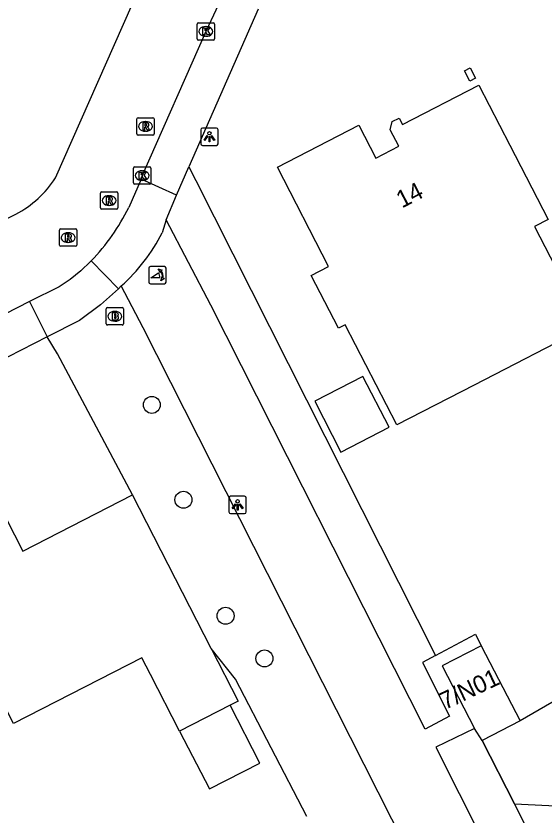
# Model space of a CAD drawing. Extents: x 162722 to 165099, y 384721 to 386283.
# Drawn here: x 163760.74 to 163791.13, y 384830.39 to 384876.43 of the extents above; entities that cross this region are included whole.
import ezdxf

# ---------------------------------------------------------------- set-up
doc = ezdxf.new("R2010")
doc.units = 0
for name, color, linetype in [('IMGEO_Berm_groen', 7, 'Continuous'), ('IMGEO_Boom', 7, 'Continuous'), ('IMGEO_Brandkraan', 7, 'Continuous'), ('IMGEO_Erf', 7, 'Continuous'), ('IMGEO_Fietspad_open', 7, 'Continuous'), ('IMGEO_Groenvoorziening', 7, 'Continuous'), ('IMGEO_Hek', 7, 'Continuous'), ('IMGEO_Kolk', 7, 'Continuous'), ('IMGEO_Lichtpunt', 7, 'Continuous'), ('IMGEO_Pand', 7, 'Continuous'), ('IMGEO_Pand_nummerreeks', 7, 'Continuous'), ('IMGEO_Poller', 7, 'Continuous'), ('IMGEO_Rijbaan_lokaal_open', 7, 'Continuous'), ('IMGEO_Rioolput', 7, 'Continuous'), ('IMGEO_Voetpad_open', 7, 'Continuous')]:
    doc.layers.add(name, color=color, linetype=linetype)

msp = doc.modelspace()

# ---------------------------------------------------------------- linework, layer by layer
at = {"layer": 'IMGEO_Berm_groen'}
for points in [[(164182.287, 385003.976), (164161.635, 384993.222), (164156.397, 384989.2), (164154.232, 384980.18), (163995.614, 384900.161), (163985.449, 384906.254), (163959.707, 384893.04), (163931.557, 384878.59), (163923.156, 384882.979), (163812.864, 384826.88), (163815.437, 384820.076), (163815.184, 384817.086), (163814.501, 384814.338), (163812.895, 384811.778), (163810.688, 384809.881), (163807.775, 384808.947), (163804.957, 384808.683), (163802.157, 384809.847), (163799.68, 384811.721), (163798.176, 384813.594), (163789.435, 384831.038)], [(163767.436, 384848.831), (163763.137, 384856.958), (163762.529, 384857.949)], [(163777.48, 384830.304), (163773.366, 384838.207), (163771.972, 384839.979)], [(163787.572, 384834.681), (163789.435, 384831.038)]]:
    msp.add_lwpolyline(points, dxfattribs=at)
at = {"layer": 'IMGEO_Boom'}
for centre in [(163768.558, 384854.02), (163770.378, 384848.557), (163772.804, 384841.869), (163775.04, 384839.409)]:
    msp.add_circle(centre, 0.489, dxfattribs=at)
at = {"layer": 'IMGEO_Brandkraan'}
for p, q in [((163765.932, 384858.699), (163765.932, 384859.551)), ((163766.007, 384859.625), (163766.859, 384859.625)), ((163766.933, 384859.551), (163766.933, 384858.699)), ((163766.42, 384859.405), (163766.445, 384859.405)), ((163766.859, 384858.625), (163766.007, 384858.625)), ((163766.443, 384858.845), (163766.418, 384858.845))]:
    msp.add_line(p, q, dxfattribs=at)
for points in [[(163765.932, 384858.699), (163765.932, 384859.551)], [(163766.007, 384859.625), (163766.859, 384859.625)], [(163766.933, 384859.551), (163766.933, 384858.699)], [(163766.28, 384859.325), (163766.28, 384858.925), (163766.493, 384858.925)], [(163766.511, 384859.325), (163766.28, 384859.325)], [(163766.459, 384859.244), (163766.405, 384859.244), (163766.405, 384859.168)], [(163766.405, 384859.168), (163766.458, 384859.168)], [(163766.467, 384859.092), (163766.405, 384859.092), (163766.405, 384859.011)], [(163766.859, 384858.625), (163766.007, 384858.625)], [(163766.405, 384859.011), (163766.467, 384859.011)]]:
    msp.add_lwpolyline(points, dxfattribs=at)
for centre, radius, start, end in [((163766.009, 384859.549), 0.0765, 91.552, 178.448), ((163766.009, 384859.549), 0.0765, 91.552, 178.448), ((163766.857, 384859.549), 0.0765, 1.552, 88.448), ((163766.857, 384859.549), 0.0765, 1.552, 88.448), ((163766.46, 384859.206), 0.0379, 267.8285, 90.9355), ((163766.468, 384859.051), 0.0404, 269.8759, 90.5077), ((163766.515, 384859.18), 0.145, 59.4692, 91.5367), ((163766.54, 384859.227), 0.0922, 285.5137, 58.1501), ((163766.545, 384859.035), 0.105, 301.3115, 78.989), ((163766.009, 384858.701), 0.0765, 181.552, 268.448), ((163766.009, 384858.701), 0.0765, 181.552, 268.448), ((163766.499, 384859.176), 0.251, 268.6676, 293.5347), ((163766.857, 384858.701), 0.0765, 271.552, 358.448), ((163766.857, 384858.701), 0.0765, 271.552, 358.448)]:
    msp.add_arc(centre, radius, start, end, dxfattribs=at)
for centre, major_axis, ratio, start_param, end_param in [((163766.419, 384859.125), (-0.387, 0.002), 0.722429, 4.712389, 7.853982), ((163766.444, 384859.125), (-0.39, 0.002), 0.717154, 1.570796, 4.712389)]:
    msp.add_ellipse(centre, major_axis=major_axis, ratio=ratio, start_param=start_param, end_param=end_param, dxfattribs=at)
at = {"layer": 'IMGEO_Erf'}
msp.add_lwpolyline([(163876.056, 384880.802), (163840.837, 384862.308), (163841.154, 384861.667), (163822.396, 384853.228), (163804.848, 384844.548), (163789.755, 384835.805)], dxfattribs=at)
at = {"layer": 'IMGEO_Fietspad_open'}
for points in [[(163769.38, 384864.694), (163769.148, 384863.937)], [(163784.89, 384839.576), (163784.143, 384839.175), (163785.689, 384836.074), (163784.283, 384835.337), (163771.953, 384859.763), (163769.38, 384864.694)], [(163802.315, 384783.336), (163802.593, 384783.556), (163802.85, 384783.8), (163803.084, 384784.066), (163803.293, 384784.352), (163803.476, 384784.656), (163803.632, 384784.974), (163803.758, 384785.305), (163803.854, 384785.646), (163803.919, 384785.995), (163803.953, 384786.348), (163803.955, 384786.702), (163803.925, 384787.055), (163803.864, 384787.404), (163803.773, 384787.746), (163803.65, 384788.079), (163803.499, 384788.4), (163803.338, 384788.677), (163797.493, 384800.236), (163768.053, 384858.461), (163766.798, 384860.873)], [(163784.89, 384839.576), (163787.19, 384840.813), (163787.523, 384840.14)], [(163787.138, 384835.371), (163784.908, 384834.301), (163801.1, 384802.109), (163807.403, 384789.577), (163807.561, 384789.273), (163807.747, 384788.984), (163807.957, 384788.713), (163808.19, 384788.462), (163808.445, 384788.232), (163808.719, 384788.026), (163809.011, 384787.846), (163809.318, 384787.692), (163809.637, 384787.567), (163809.966, 384787.47), (163810.303, 384787.403), (163810.644, 384787.367), (163810.987, 384787.361), (163811.329, 384787.386), (163811.667, 384787.441), (163811.814, 384787.475)]]:
    msp.add_lwpolyline(points, dxfattribs=at)
msp.add_arc((163759.982, 384868.534), 10.254, 311.6601, 333.3656, dxfattribs=at)
at = {"layer": 'IMGEO_Groenvoorziening'}
for points in [[(163770.692, 384867.742), (163771.093, 384866.945), (163784.89, 384839.576)], [(163789.435, 384831.038), (163800.899, 384830.469)]]:
    msp.add_lwpolyline(points, dxfattribs=at)
at = {"layer": 'IMGEO_Hek'}
for points in [[(163959.707, 384893.04), (163931.557, 384878.59), (163923.156, 384882.979), (163812.864, 384826.88), (163815.437, 384820.076), (163815.184, 384817.086), (163814.501, 384814.338), (163812.895, 384811.778), (163810.688, 384809.881), (163807.775, 384808.947), (163804.957, 384808.683), (163802.157, 384809.847), (163799.68, 384811.721), (163798.176, 384813.594), (163789.435, 384831.038)], [(163777.48, 384830.304), (163773.366, 384838.207), (163771.972, 384839.979)], [(163789.435, 384831.038), (163787.572, 384834.681)], [(163789.435, 384831.038), (163800.899, 384830.469)]]:
    msp.add_lwpolyline(points, dxfattribs=at)
at = {"layer": 'IMGEO_Kolk'}
for p, q in [((163771.167, 384875.115), (163771.167, 384875.967)), ((163771.242, 384876.041), (163772.094, 384876.041)), ((163771.655, 384875.821), (163771.68, 384875.821)), ((163772.168, 384875.967), (163772.168, 384875.115)), ((163771.678, 384875.261), (163771.653, 384875.261)), ((163772.094, 384875.041), (163771.242, 384875.041)), ((163767.502, 384866.808), (163767.502, 384867.66)), ((163767.577, 384867.734), (163768.429, 384867.734)), ((163767.99, 384867.514), (163768.015, 384867.514)), ((163768.503, 384867.66), (163768.503, 384866.808)), ((163768.013, 384866.954), (163767.988, 384866.954)), ((163768.429, 384866.734), (163767.577, 384866.734))]:
    msp.add_line(p, q, dxfattribs=at)
for points in [[(163771.167, 384875.115), (163771.167, 384875.967)], [(163771.242, 384876.041), (163772.094, 384876.041)], [(163771.488, 384875.741), (163771.611, 384875.741), (163771.611, 384875.59), (163771.741, 384875.741), (163771.905, 384875.741), (163771.759, 384875.59), (163771.912, 384875.341), (163771.76, 384875.341), (163771.675, 384875.505), (163771.611, 384875.438), (163771.611, 384875.341), (163771.488, 384875.341), (163771.488, 384875.741)], [(163772.168, 384875.967), (163772.168, 384875.115)], [(163772.094, 384875.041), (163771.242, 384875.041)], [(163767.502, 384866.808), (163767.502, 384867.66)], [(163767.577, 384867.734), (163768.429, 384867.734)], [(163767.823, 384867.434), (163767.946, 384867.434), (163767.946, 384867.283), (163768.076, 384867.434), (163768.24, 384867.434), (163768.094, 384867.283), (163768.247, 384867.034), (163768.095, 384867.034), (163768.01, 384867.198), (163767.946, 384867.131), (163767.946, 384867.034), (163767.823, 384867.034), (163767.823, 384867.434)], [(163768.503, 384867.66), (163768.503, 384866.808)], [(163768.429, 384866.734), (163767.577, 384866.734)]]:
    msp.add_lwpolyline(points, dxfattribs=at)
for centre, start, end in [((163771.244, 384875.965), 91.552, 178.448), ((163771.244, 384875.965), 91.552, 178.448), ((163772.092, 384875.965), 1.552, 88.448), ((163772.092, 384875.965), 1.552, 88.448), ((163771.244, 384875.117), 181.552, 268.448), ((163771.244, 384875.117), 181.552, 268.448), ((163772.092, 384875.117), 271.552, 358.448), ((163772.092, 384875.117), 271.552, 358.448), ((163767.579, 384867.658), 91.552, 178.448), ((163767.579, 384867.658), 91.552, 178.448), ((163768.427, 384867.658), 1.552, 88.448), ((163768.427, 384867.658), 1.552, 88.448), ((163767.579, 384866.81), 181.552, 268.448), ((163767.579, 384866.81), 181.552, 268.448), ((163768.427, 384866.81), 271.552, 358.448), ((163768.427, 384866.81), 271.552, 358.448)]:
    msp.add_arc(centre, 0.0765, start, end, dxfattribs=at)
for centre, major_axis, ratio, start_param, end_param in [((163771.654, 384875.541), (-0.387, 0.002), 0.722429, 4.712389, 7.853982), ((163771.679, 384875.541), (-0.39, 0.002), 0.717154, 1.570796, 4.712389), ((163767.989, 384867.234), (-0.387, 0.002), 0.722429, 4.712389, 7.853982), ((163768.014, 384867.234), (-0.39, 0.002), 0.717154, 1.570796, 4.712389)]:
    msp.add_ellipse(centre, major_axis=major_axis, ratio=ratio, start_param=start_param, end_param=end_param, dxfattribs=at)
at = {"layer": 'IMGEO_Lichtpunt'}
for p, q in [((163771.374, 384869.878), (163771.374, 384869.071)), ((163771.374, 384869.878), (163771.374, 384869.071)), ((163772.276, 384869.973), (163771.468, 384869.973)), ((163772.276, 384869.973), (163771.468, 384869.973)), ((163772.37, 384869.071), (163772.37, 384869.878)), ((163772.37, 384869.071), (163772.37, 384869.878)), ((163771.468, 384868.977), (163772.276, 384868.977)), ((163771.468, 384868.977), (163772.276, 384868.977)), ((163772.996, 384848.663), (163772.996, 384847.856)), ((163772.996, 384848.663), (163772.996, 384847.856)), ((163773.898, 384848.758), (163773.09, 384848.758)), ((163773.898, 384848.758), (163773.09, 384848.758)), ((163773.992, 384847.856), (163773.992, 384848.663)), ((163773.992, 384847.856), (163773.992, 384848.663)), ((163773.09, 384847.762), (163773.898, 384847.762)), ((163773.09, 384847.762), (163773.898, 384847.762))]:
    msp.add_line(p, q, dxfattribs=at)
for points in [[(163771.748, 384869.542), (163771.787, 384869.514), (163771.599, 384869.252), (163771.561, 384869.279), (163771.748, 384869.542)], [(163771.85, 384869.494), (163771.897, 384869.494), (163771.897, 384869.172), (163771.85, 384869.172), (163771.85, 384869.494)], [(163771.96, 384869.514), (163771.998, 384869.541), (163772.185, 384869.279), (163772.146, 384869.251), (163771.96, 384869.514)], [(163773.37, 384848.327), (163773.409, 384848.299), (163773.221, 384848.037), (163773.183, 384848.064), (163773.37, 384848.327)], [(163773.472, 384848.279), (163773.519, 384848.279), (163773.519, 384847.957), (163773.472, 384847.957), (163773.472, 384848.279)], [(163773.582, 384848.299), (163773.62, 384848.326), (163773.807, 384848.064), (163773.768, 384848.036), (163773.582, 384848.299)]]:
    msp.add_lwpolyline(points, dxfattribs=at)
for centre in [(163771.873, 384869.676), (163773.495, 384848.461)]:
    msp.add_circle(centre, 0.0994, dxfattribs=at)
for centre, start, end in [((163771.468, 384869.878), 90, 180), ((163771.468, 384869.878), 90, 180), ((163772.276, 384869.878), 0, 90), ((163772.276, 384869.878), 0, 90), ((163771.468, 384869.071), 180, 270), ((163771.468, 384869.071), 180, 270), ((163772.276, 384869.071), 270, 0), ((163772.276, 384869.071), 270, 360), ((163773.09, 384848.663), 90, 180), ((163773.09, 384848.663), 90, 180), ((163773.898, 384848.663), 0, 90), ((163773.898, 384848.663), 0, 90), ((163773.09, 384847.856), 180, 270), ((163773.09, 384847.856), 180, 270), ((163773.898, 384847.856), 270, 0), ((163773.898, 384847.856), 270, 360)]:
    msp.add_arc(centre, 0.0946, start, end, dxfattribs=at)
at = {"layer": 'IMGEO_Pand'}
for points in [[(163787.183, 384872.853), (163786.854, 384872.684), (163786.552, 384873.271), (163786.881, 384873.44), (163787.183, 384872.853)], [(163789.17, 384868.995), (163791.377, 384864.707), (163790.592, 384864.303), (163793.581, 384858.497), (163787.106, 384855.164), (163782.66, 384852.875), (163779.692, 384858.64), (163779.295, 384858.435), (163777.725, 384861.484), (163778.732, 384862.002), (163775.785, 384867.728), (163780.471, 384870.141), (163781.446, 384868.248), (163782.771, 384868.93), (163782.284, 384869.876), (163782.393, 384870.342), (163782.802, 384870.552), (163782.99, 384870.188), (163787.389, 384872.453), (163789.17, 384868.995)], [(163777.933, 384854.235), (163779.442, 384851.304), (163782.219, 384852.734), (163780.71, 384855.665), (163777.933, 384854.235)], [(163749.509, 384839.691), (163746.634, 384845.301), (163758.231, 384851.244), (163761.125, 384845.596), (163767.436, 384848.831)], [(163771.972, 384839.979), (163767.436, 384848.831)], [(163770.146, 384835.223), (163768.472, 384838.488), (163767.984, 384839.44), (163760.593, 384835.653), (163758.142, 384840.435), (163754.931, 384838.79), (163751.296, 384836.928)], [(163771.972, 384839.979), (163773.522, 384836.953), (163773.061, 384836.717)], [(163787.523, 384840.14), (163785.278, 384838.984), (163787.138, 384835.371)], [(163787.523, 384840.14), (163789.755, 384835.805)], [(163773.061, 384836.717), (163770.146, 384835.223)], [(163770.146, 384835.223), (163771.879, 384831.902), (163774.77, 384833.383), (163773.061, 384836.717)], [(163789.755, 384835.805), (163787.572, 384834.681)], [(163787.572, 384834.681), (163787.138, 384835.371)]]:
    msp.add_lwpolyline(points, dxfattribs=at)
at = {"layer": 'IMGEO_Poller'}
for p, q in [((163768.383, 384861.9), (163768.383, 384861.093)), ((163768.383, 384861.9), (163768.383, 384861.093)), ((163769.285, 384861.995), (163768.477, 384861.995)), ((163769.285, 384861.995), (163768.477, 384861.995)), ((163769.379, 384861.093), (163769.379, 384861.9)), ((163769.379, 384861.093), (163769.379, 384861.9)), ((163768.477, 384860.998), (163769.285, 384860.998)), ((163768.477, 384860.998), (163769.285, 384860.998))]:
    msp.add_line(p, q, dxfattribs=at)
for points in [[(163769.062, 384861.724), (163769.05, 384861.651), (163768.925, 384861.856)], [(163768.925, 384861.856), (163769.156, 384861.79), (163769.085, 384861.758)], [(163769.018, 384861.351), (163768.505, 384861.351), (163768.935, 384861.626)], [(163769.078, 384861.179), (163769.144, 384861.41), (163769.174, 384861.342)], [(163769.21, 384861.315), (163769.282, 384861.304), (163769.078, 384861.179)]]:
    msp.add_lwpolyline(points, dxfattribs=at)
for centre, radius, start, end in [((163768.477, 384861.9), 0.0946, 90, 180), ((163768.477, 384861.9), 0.0946, 90, 180), ((163769.285, 384861.9), 0.0946, 0, 90), ((163769.285, 384861.9), 0.0946, 0, 90), ((163768.69, 384861.401), 0.332, 351.3247, 42.4854), ((163768.704, 384861.411), 0.476, 351.7527, 41.1691), ((163768.704, 384861.411), 0.516, 349.3569, 42.2912), ((163768.477, 384861.093), 0.0946, 180, 270), ((163768.477, 384861.093), 0.0946, 180, 270), ((163769.285, 384861.093), 0.0946, 270, 0), ((163769.285, 384861.093), 0.0946, 270, 0)]:
    msp.add_arc(centre, radius, start, end, dxfattribs=at)
at = {"layer": 'IMGEO_Rijbaan_lokaal_open'}
for points in [[(163763.01, 384867.097), (163767.881, 384878.148)], [(163772.676, 384877.737), (163771.668, 384875.541), (163768.003, 384867.234), (163767.945, 384867.026)], [(163767.945, 384867.026), (163767.225, 384865.392)], [(163733.052, 384850.955), (163760.739, 384865.014)], [(163765.072, 384862.326), (163765.028, 384862.28), (163764.47, 384861.74), (163763.865, 384861.253), (163763.219, 384860.821), (163761.507, 384859.988)], [(163761.507, 384859.988), (163760.102, 384859.244), (163758.493, 384858.439)]]:
    msp.add_lwpolyline(points, dxfattribs=at)
for centre, radius, start, end in [((163757.832, 384870.462), 6.175, 298.0788, 326.9764), ((163756.434, 384870.681), 12.018, 315.9555, 333.8901)]:
    msp.add_arc(centre, radius, start, end, dxfattribs=at)
at = {"layer": 'IMGEO_Rioolput'}
for p, q in [((163767.697, 384869.644), (163767.697, 384870.496)), ((163767.772, 384870.57), (163768.624, 384870.57)), ((163768.185, 384870.35), (163768.21, 384870.35)), ((163768.698, 384870.496), (163768.698, 384869.644)), ((163768.208, 384869.79), (163768.183, 384869.79)), ((163768.624, 384869.57), (163767.772, 384869.57)), ((163765.6, 384865.371), (163765.6, 384866.223)), ((163765.675, 384866.297), (163766.527, 384866.297)), ((163766.088, 384866.077), (163766.113, 384866.077)), ((163766.601, 384866.223), (163766.601, 384865.371)), ((163766.111, 384865.517), (163766.086, 384865.517)), ((163766.527, 384865.297), (163765.675, 384865.297)), ((163763.311, 384864.16), (163764.163, 384864.16)), ((163763.236, 384863.234), (163763.236, 384864.086)), ((163763.724, 384863.94), (163763.749, 384863.94)), ((163764.237, 384864.086), (163764.237, 384863.234)), ((163763.747, 384863.38), (163763.722, 384863.38)), ((163764.163, 384863.16), (163763.311, 384863.16))]:
    msp.add_line(p, q, dxfattribs=at)
for points in [[(163767.697, 384869.644), (163767.697, 384870.496)], [(163767.772, 384870.57), (163768.624, 384870.57)], [(163768.286, 384870.268), (163768.034, 384870.27), (163768.034, 384869.87)], [(163768.212, 384870.189), (163768.158, 384870.189), (163768.158, 384870.108)], [(163768.698, 384870.496), (163768.698, 384869.644)], [(163768.034, 384869.87), (163768.158, 384869.87), (163768.158, 384870.032), (163768.169, 384870.032)], [(163768.158, 384870.108), (163768.21, 384870.108)], [(163768.216, 384870.003), (163768.287, 384869.87), (163768.427, 384869.87), (163768.362, 384869.996)], [(163768.624, 384869.57), (163767.772, 384869.57)], [(163765.6, 384865.371), (163765.6, 384866.223)], [(163765.675, 384866.297), (163766.527, 384866.297)], [(163766.189, 384865.995), (163765.937, 384865.997), (163765.937, 384865.597)], [(163766.601, 384866.223), (163766.601, 384865.371)], [(163765.937, 384865.597), (163766.061, 384865.597), (163766.061, 384865.759), (163766.072, 384865.759)], [(163766.115, 384865.916), (163766.061, 384865.916), (163766.061, 384865.835)], [(163766.061, 384865.835), (163766.113, 384865.835)], [(163766.119, 384865.73), (163766.19, 384865.597), (163766.33, 384865.597), (163766.265, 384865.723)], [(163766.527, 384865.297), (163765.675, 384865.297)], [(163763.311, 384864.16), (163764.163, 384864.16)], [(163763.236, 384863.234), (163763.236, 384864.086)], [(163763.825, 384863.858), (163763.573, 384863.86), (163763.573, 384863.46)], [(163763.751, 384863.779), (163763.697, 384863.779), (163763.697, 384863.698)], [(163763.697, 384863.698), (163763.749, 384863.698)], [(163764.237, 384864.086), (163764.237, 384863.234)], [(163763.573, 384863.46), (163763.697, 384863.46), (163763.697, 384863.622), (163763.708, 384863.622)], [(163763.755, 384863.593), (163763.826, 384863.46), (163763.966, 384863.46), (163763.901, 384863.586)], [(163764.163, 384863.16), (163763.311, 384863.16)]]:
    msp.add_lwpolyline(points, dxfattribs=at)
for centre, radius, start, end in [((163767.774, 384870.494), 0.0765, 91.552, 178.448), ((163767.774, 384870.494), 0.0765, 91.552, 178.448), ((163768.218, 384870.093), 0.0964, 77.0061, 93.1865), ((163768.232, 384870.15), 0.0378, 276.6634, 79.6772), ((163768.285, 384870.158), 0.109, 350.3612, 89.416), ((163768.283, 384870.158), 0.112, 277.5842, 350.9817), ((163768.622, 384870.494), 0.0765, 1.552, 88.448), ((163768.622, 384870.494), 0.0765, 1.552, 88.448), ((163768.168, 384869.979), 0.0533, 26.0293, 88.6989), ((163768.194, 384870.297), 0.19, 274.7715, 282.9687), ((163768.267, 384869.943), 0.108, 29.5134, 73.7905), ((163767.774, 384869.646), 0.0765, 181.552, 268.448), ((163767.774, 384869.646), 0.0765, 181.552, 268.448), ((163768.622, 384869.646), 0.0765, 271.552, 358.448), ((163768.622, 384869.646), 0.0765, 271.552, 358.448), ((163765.677, 384866.221), 0.0765, 91.552, 178.448), ((163765.677, 384866.221), 0.0765, 91.552, 178.448), ((163766.188, 384865.885), 0.109, 350.3612, 89.416), ((163766.525, 384866.221), 0.0765, 1.552, 88.448), ((163766.525, 384866.221), 0.0765, 1.552, 88.448), ((163766.071, 384865.706), 0.0533, 26.0293, 88.6989), ((163766.097, 384866.024), 0.19, 274.7715, 282.9687), ((163766.121, 384865.82), 0.0964, 77.0061, 93.1865), ((163766.135, 384865.877), 0.0378, 276.6634, 79.6772), ((163766.186, 384865.885), 0.112, 277.5842, 350.9817), ((163766.17, 384865.67), 0.108, 29.5134, 73.7905), ((163765.677, 384865.373), 0.0765, 181.552, 268.448), ((163765.677, 384865.373), 0.0765, 181.552, 268.448), ((163766.525, 384865.373), 0.0765, 271.552, 358.448), ((163766.525, 384865.373), 0.0765, 271.552, 358.448), ((163763.313, 384864.084), 0.0765, 91.552, 178.448), ((163763.313, 384864.084), 0.0765, 91.552, 178.448), ((163764.161, 384864.084), 0.0765, 1.552, 88.448), ((163764.161, 384864.084), 0.0765, 1.552, 88.448), ((163763.733, 384863.887), 0.19, 274.7715, 282.9687), ((163763.757, 384863.683), 0.0964, 77.0061, 93.1865), ((163763.771, 384863.74), 0.0378, 276.6634, 79.6772), ((163763.824, 384863.748), 0.109, 350.3612, 89.416), ((163763.822, 384863.748), 0.112, 277.5842, 350.9817), ((163763.313, 384863.236), 0.0765, 181.552, 268.448), ((163763.313, 384863.236), 0.0765, 181.552, 268.448), ((163763.707, 384863.569), 0.0533, 26.0293, 88.6989), ((163763.806, 384863.533), 0.108, 29.5134, 73.7905), ((163764.161, 384863.236), 0.0765, 271.552, 358.448), ((163764.161, 384863.236), 0.0765, 271.552, 358.448)]:
    msp.add_arc(centre, radius, start, end, dxfattribs=at)
for centre, major_axis, ratio, start_param, end_param in [((163768.184, 384870.07), (-0.387, 0.002), 0.722429, 4.712389, 7.853982), ((163768.209, 384870.07), (-0.39, 0.002), 0.717154, 1.570796, 4.712389), ((163766.087, 384865.797), (-0.387, 0.002), 0.722429, 4.712389, 7.853982), ((163766.112, 384865.797), (-0.39, 0.002), 0.717154, 1.570796, 4.712389), ((163763.723, 384863.66), (-0.387, 0.002), 0.722429, 4.712389, 7.853982), ((163763.748, 384863.66), (-0.39, 0.002), 0.717154, 1.570796, 4.712389)]:
    msp.add_ellipse(centre, major_axis=major_axis, ratio=ratio, start_param=start_param, end_param=end_param, dxfattribs=at)
at = {"layer": 'IMGEO_Voetpad_open'}
for points in [[(163774.677, 384876.823), (163770.692, 384867.742)], [(163769.977, 384866.113), (163770.692, 384867.742)], [(163769.977, 384866.113), (163767.945, 384867.026)], [(163769.38, 384864.694), (163769.977, 384866.113)], [(163766.646, 384860.702), (163765.072, 384862.326)], [(163766.646, 384860.702), (163765.603, 384859.783), (163764.39, 384858.887), (163762.529, 384857.949)], [(163766.798, 384860.873), (163766.646, 384860.702)], [(163761.507, 384859.988), (163762.529, 384857.949)], [(163762.529, 384857.949), (163759.521, 384856.413)]]:
    msp.add_lwpolyline(points, dxfattribs=at)

# ---------------------------------------------------------------- texts
at = {"layer": 'IMGEO_Pand_nummerreeks'}
for s, rotation, p in [('14', 27.2357, (163782.956, 384865.336)), ('7/N01', 25.2011, (163785.434, 384836.438))]:
    msp.add_text(s, height=1, rotation=rotation, dxfattribs=at).set_placement(p)

doc.saveas('drawing.dxf')
